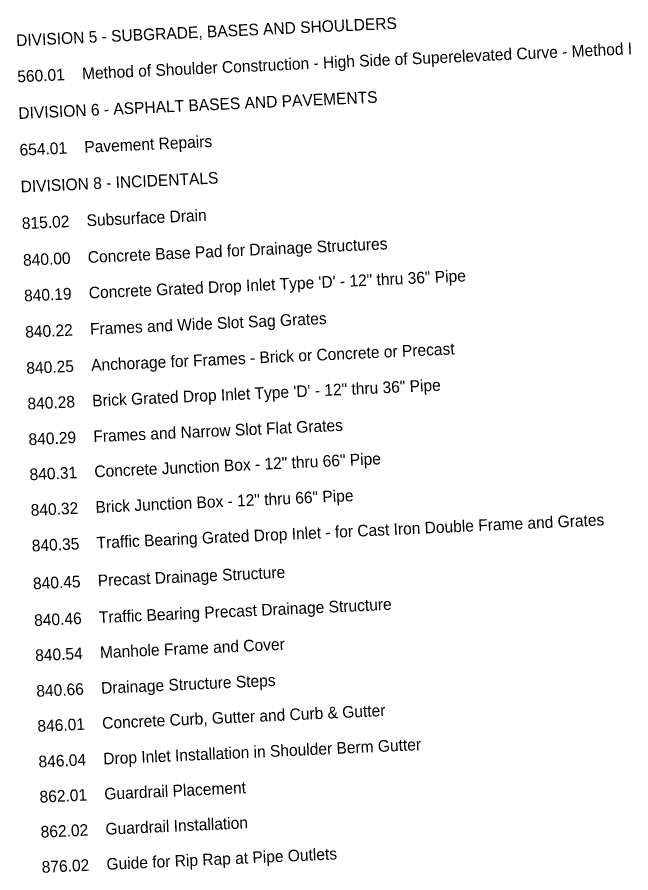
# Model space of a CAD drawing. Extents: x 1190067 to 1192950, y 891516 to 893460.
# Drawn here: x 1191429.9 to 1191513, y 892115.9 to 892231.8 of the extents above; entities that cross this region are included whole.
import ezdxf

# ---------------------------------------------------------------- set-up
doc = ezdxf.new("R2010")
doc.units = 0
doc.layers.add('Sheet Data Text CELL', color=7, linetype='Continuous')

msp = doc.modelspace()

# ---------------------------------------------------------------- texts
at = {"layer": 'Sheet Data Text CELL'}
for s, p in [('DIVISION 5 - SUBGRADE, BASES AND SHOULDERS', (1191429.82, 892227.91)), ('560.01    Method of Shoulder Construction - High Side of Superelevated Curve - Method I', (1191429.97, 892223.01)), ('DIVISION 6 - ASPHALT BASES AND PAVEMENTS', (1191430.12, 892218.04)), ('654.01    Pavement Repairs', (1191430.28, 892213.07)), ('DIVISION 8 - INCIDENTALS', (1191430.43, 892208.09)), ('815.02    Subsurface Drain', (1191430.59, 892203.12)), ('840.00    Concrete Base Pad for Drainage Structures', (1191430.75, 892198.14)), ('840.19    Concrete Grated Drop Inlet Type \'D\' - 12" thru 36" Pipe', (1191430.89, 892193.32)), ('840.22    Frames and Wide Slot Sag Grates', (1191431.05, 892188.41)), ('840.25    Anchorage for Frames - Brick or Concrete or Precast', (1191431.2, 892183.51)), ('840.28    Brick Grated Drop Inlet Type \'D\' - 12" thru 36" Pipe', (1191431.35, 892178.69)), ('840.29    Frames and Narrow Slot Flat Grates', (1191431.5, 892173.86)), ('840.31    Concrete Junction Box - 12" thru 66" Pipe', (1191431.64, 892169.1)), ('840.32    Brick Junction Box - 12" thru 66" Pipe', (1191431.79, 892164.28)), ('840.35    Traffic Bearing Grated Drop Inlet - for Cast Iron Double Frame and Grates', (1191431.94, 892159.45)), ('840.45    Precast Drainage Structure', (1191432.1, 892154.33)), ('840.46    Traffic Bearing Precast Drainage Structure', (1191432.26, 892149.35)), ('840.54    Manhole Frame and Cover', (1191432.4, 892144.6)), ('840.66    Drainage Structure Steps', (1191432.55, 892139.77)), ('846.01    Concrete Curb, Gutter and Curb & Gutter', (1191432.7, 892135.02)), ('846.04    Drop Inlet Installation in Shoulder Berm Gutter', (1191432.85, 892130.19)), ('862.01    Guardrail Placement', (1191432.99, 892125.43)), ('862.02    Guardrail Installation', (1191433.14, 892120.68)), ('876.02    Guide for Rip Rap at Pipe Outlets', (1191433.28, 892115.92))]:
    msp.add_text(s, height=1.5748, rotation=2.6195, dxfattribs=at).set_placement(p)

doc.saveas('drawing.dxf')
